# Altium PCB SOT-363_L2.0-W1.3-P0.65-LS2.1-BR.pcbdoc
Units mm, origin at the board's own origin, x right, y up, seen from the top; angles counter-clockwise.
Board outline 15.45 x 15.2 mm, 2 copper layers (Top Layer, Bottom Layer), stack 0.07 mm thick; 1 components, 0 nets, 6 pads, 0 vias.
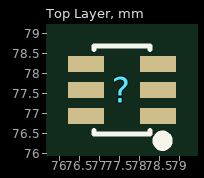
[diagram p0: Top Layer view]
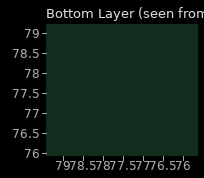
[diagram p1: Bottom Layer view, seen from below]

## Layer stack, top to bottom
Top Solder Mask Layer: solder mask 0.01, Dk 3.3
Top Layer: signal copper 0.035
Bottom Layer: signal copper 0.035
Bottom Solder Mask Layer: solder mask 0.01, Dk 3.3

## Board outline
85.297,69.85 69.85,69.85 69.85,85.047 85.297,85.047

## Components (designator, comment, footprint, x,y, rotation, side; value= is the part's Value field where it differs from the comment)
? "SOT-363_L2.0-W1.3-P0.65-LS2.1-BR" SOT-363_L2.0-W1.3-P0.65-LS2.1-BR 77.55,77.597 r0 top

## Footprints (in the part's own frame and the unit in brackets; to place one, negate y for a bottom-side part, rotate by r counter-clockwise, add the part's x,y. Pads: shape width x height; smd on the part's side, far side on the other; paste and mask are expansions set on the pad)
SOT-363_L2.0-W1.3-P0.65-LS2.1-BR [mm]
  rect 0.9x0.4 smd paste+0 mask+0.051: 1(0.9,-0.65) 2(0.9,0) 3(0.9,0.65) 4(-0.9,0.65) 5(-0.9,0) 6(-0.9,-0.65)
  silkscreen extent -0.7,-1.4 1.14,1.1

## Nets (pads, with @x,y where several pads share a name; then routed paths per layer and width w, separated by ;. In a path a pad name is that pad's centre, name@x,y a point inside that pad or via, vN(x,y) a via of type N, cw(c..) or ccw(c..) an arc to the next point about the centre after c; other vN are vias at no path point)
pads on no net: ?.1 ?.2 ?.3 ?.4 ?.5 ?.6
